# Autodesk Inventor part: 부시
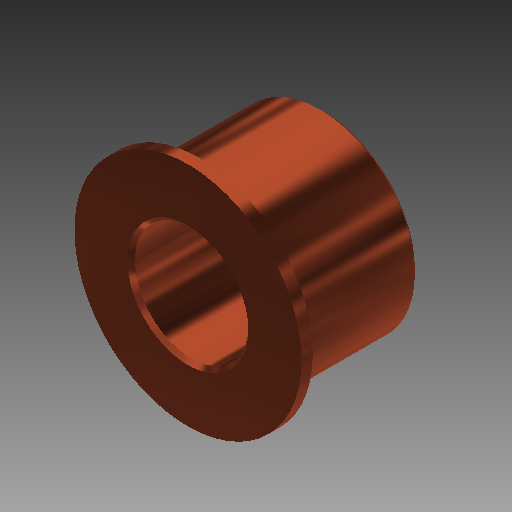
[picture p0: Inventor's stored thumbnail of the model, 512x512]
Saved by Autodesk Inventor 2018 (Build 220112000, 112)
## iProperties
Created: 2015-10
Part Number: 부시
Document SubType Name: Modeling
Designer: mdu
Density: 7.86 g/cm^3
Material: 강철, 연강
Mass: 246.97 g
Surface Area: 129.264 cm^2
Volume: 31.4212 cm^3
Appearance: 구리 - 새틴
Author: mdu
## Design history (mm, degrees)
sketch "스케치1"
  geometry: C1 r 31 at (0, 0) reference; C2 r 25 at (0, 0) reference; C3 r 30 at (0, 0) reference; 1 further point
  node "참조1"
  node "참조2"
  node "참조4"
extrude "돌출1" new body sketch "스케치1" distance "d0" = 3; taper "d1" = 0 deg
extrude "돌출2" join sketch "스케치1" distance "d2" = 36; taper "d3" = 0 deg
chamfer "모따기1" distance "d6" = 1; stored, may be unused: second distance "d7" = 2, angle "d8" = 45 deg
sketch "스케치3"
  geometry: C1 r 15 at (0, 0); 1 further point
  constraints: 1 centre point, 1 coincident
  dimensions: "d13" = 30 diameter of C1
extrude "돌출4" cut sketch "스케치3" extent not by distance; stored distance "d14" = 10; taper "d15" = 0 deg
chamfer "모따기3" distance "d16" = 1; stored, may be unused: second distance "d17" = 2, angle "d18" = 45 deg
node "솔리드1"
